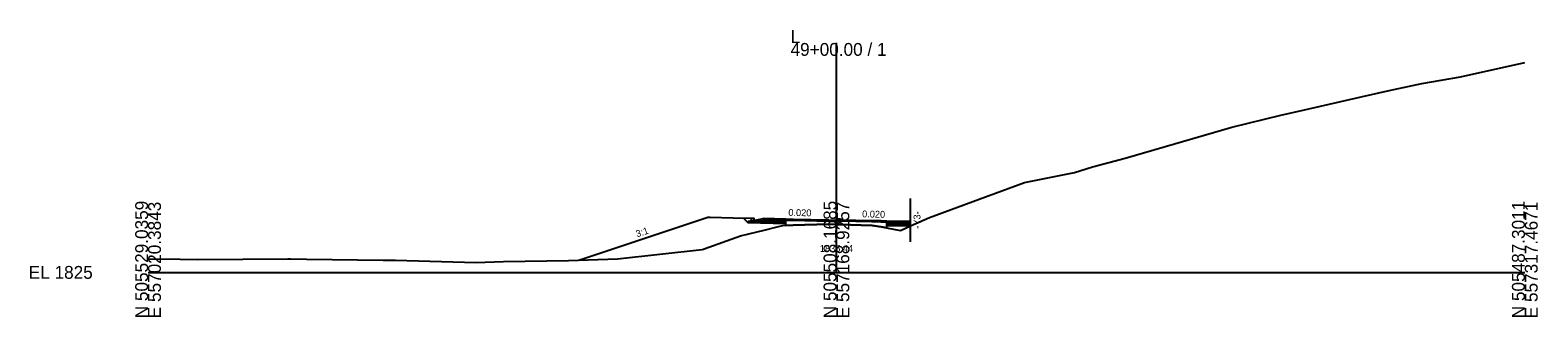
# Model space of a CAD drawing. Extents: x -26 to 4603, y -10 to 4703.
# Drawn here: x 1474.3 to 1802.8, y 4395.3 to 4457.8 of the extents above; entities that cross this region are included whole.
import ezdxf

# ---------------------------------------------------------------- set-up
doc = ezdxf.new("R2010")
doc.units = 0
for name, color, linetype in [('Default', 7, 'Continuous'), ('Exist Cross Section Cell', 7, 'Continuous'), ('Exist XS Ground Line', 7, 'Continuous'), ('Prop CMT Pvmt Course 1', 7, 'Continuous'), ('Prop CMT Pvmt Course 2', 7, 'Continuous'), ('Prop CMT Pvmt Course 3', 7, 'Continuous'), ('Prop CMT Pvmt Milling', 7, 'Continuous'), ('Prop CMT Shear Line', 7, 'Continuous'), ('Prop CMT Shld Paved Course 2', 7, 'Continuous'), ('Prop CMT Shld Paved Course 3', 7, 'Continuous'), ('Prop CMT Subgrade Earthwork', 7, 'Continuous'), ('Prop Conc Curb and Gutter', 7, 'Continuous'), ('Prop XS Finish Grade', 7, 'Continuous'), ('Prop XS Label Text', 7, 'Continuous'), ('Prop XS Shear Point Element', 7, 'Continuous'), ('Prop XS Shear Point Label', 7, 'Continuous'), ('Prop XS SS Elevation Text', 7, 'Continuous'), ('Scratch_Level_9', 7, 'Continuous')]:
    doc.layers.add(name, color=color, linetype=linetype)

msp = doc.modelspace()

# ---------------------------------------------------------------- linework, layer by layer
at = {"layer": 'Exist Cross Section Cell'}
for p, q in [((1650, 4405), (1650, 4455)), ((1500, 4405), (1650, 4405)), ((1650, 4405), (1800, 4405))]:
    msp.add_line(p, q, dxfattribs=at)
at = {"layer": 'Exist XS Ground Line'}
msp.add_lwpolyline([(1500, 4407.94), (1506.96, 4407.86), (1510.83, 4407.79), (1530.46, 4407.94), (1531.02, 4407.94), (1534.5, 4407.9), (1551.22, 4407.69), (1553.95, 4407.67), (1571.42, 4407.17), (1577.45, 4407.35), (1591.61, 4407.57), (1602.29, 4407.97), (1620.72, 4410.01), (1621, 4410.05), (1621.16, 4410.11), (1629.12, 4412.94), (1632.73, 4413.85), (1634.22, 4414.18), (1637.11, 4414.93), (1638.33, 4415.23), (1640.58, 4415.29), (1648.26, 4415.48), (1650.65, 4415.43), (1657.82, 4415.25), (1659.75, 4414.92), (1663.93, 4414.12), (1666.13, 4415.15), (1670.27, 4416.93), (1681.11, 4420.94), (1690.99, 4424.58), (1701.87, 4426.78), (1705.77, 4428.03), (1712.92, 4429.91), (1736.17, 4436.65), (1746.83, 4439.29), (1751.99, 4440.46), (1764.32, 4443.3), (1770.47, 4444.68), (1777.55, 4446.15), (1785.98, 4447.64), (1800, 4450.74)], dxfattribs=at)
at = {"layer": 'Prop CMT Pvmt Course 1'}
for points in [[(1639, 4416.63), (1634, 4416.73), (1634, 4416.48), (1634, 4416.48), (1639, 4416.38), (1639, 4416.38), (1639, 4416.38), (1639, 4416.63), (1639, 4416.63)], [(1650, 4416.41), (1650, 4416.41), (1650, 4415.44), (1650, 4415.44), (1650, 4415.44), (1648.26, 4415.48), (1648.26, 4415.48), (1640.58, 4415.29), (1640.58, 4415.29), (1639, 4415.25), (1639, 4415.25), (1639, 4416.63), (1640.58, 4416.6), (1640.58, 4416.6), (1648.26, 4416.45), (1648.26, 4416.45), (1650, 4416.41)], [(1659.75, 4416.22), (1657.82, 4416.26), (1657.82, 4416.26), (1650.65, 4416.4), (1650.65, 4416.4), (1650, 4416.41), (1650, 4415.44), (1650, 4415.44), (1650.65, 4415.43), (1650.65, 4415.43), (1657.82, 4415.25), (1657.82, 4415.25), (1659.75, 4414.92), (1659.75, 4414.92), (1661, 4414.68), (1661, 4414.68), (1661, 4416.19), (1659.75, 4416.22), (1659.75, 4416.22)], [(1661, 4416.19), (1661, 4416.19), (1661, 4415.94), (1661, 4415.94), (1661, 4415.94), (1666.14, 4415.84), (1666.14, 4415.84), (1666.14, 4416.09), (1661, 4416.19)]]:
    msp.add_lwpolyline(points, dxfattribs=at)
at = {"layer": 'Prop CMT Pvmt Course 2'}
for points in [[(1639, 4416.38), (1634, 4416.48), (1634, 4416.15), (1634, 4416.15), (1639, 4416.05), (1639, 4416.05), (1639, 4416.05), (1639, 4416.38), (1639, 4416.38)], [(1661, 4415.94), (1661, 4415.94), (1661, 4415.61), (1661, 4415.61), (1661, 4415.61), (1666.14, 4415.51), (1666.14, 4415.51), (1666.14, 4415.84), (1661, 4415.94)]]:
    msp.add_lwpolyline(points, dxfattribs=at)
at = {"layer": 'Prop CMT Pvmt Course 3'}
for points in [[(1639, 4416.05), (1634, 4416.15), (1634, 4415.78), (1634, 4415.78), (1639, 4415.68), (1639, 4415.68), (1639, 4415.68), (1639, 4416.05), (1639, 4416.05)], [(1661, 4415.61), (1661, 4415.61), (1661, 4415.24), (1661, 4415.24), (1661, 4415.24), (1666.14, 4415.13), (1666.14, 4415.13), (1666.14, 4415.51), (1661, 4415.61)]]:
    msp.add_lwpolyline(points, dxfattribs=at)
at = {"layer": 'Prop CMT Pvmt Milling'}
for points in [[(1639, 4415.25), (1640.58, 4415.29), (1640.58, 4415.29), (1648.26, 4415.48), (1648.26, 4415.48), (1650, 4415.44), (1650, 4415.44)], [(1661, 4414.68), (1659.75, 4414.92), (1659.75, 4414.92), (1657.82, 4415.25), (1657.82, 4415.25), (1650.65, 4415.43), (1650.65, 4415.43), (1650, 4415.44)]]:
    msp.add_lwpolyline(points, dxfattribs=at)
at = {"layer": 'Prop CMT Shld Paved Course 2'}
for points in [[(1650, 4416.16), (1650, 4416.16), (1650, 4415.44), (1650, 4415.44), (1650, 4415.44), (1648.26, 4415.48), (1648.26, 4415.48), (1640.58, 4415.29), (1640.58, 4415.29), (1639, 4415.25), (1639, 4415.25), (1639, 4416.38), (1640.58, 4416.35), (1640.58, 4416.35), (1648.26, 4416.2), (1648.26, 4416.2), (1650, 4416.16)], [(1659.75, 4415.97), (1657.82, 4416.01), (1657.82, 4416.01), (1650.65, 4416.15), (1650.65, 4416.15), (1650, 4416.16), (1650, 4415.44), (1650, 4415.44), (1650.65, 4415.43), (1650.65, 4415.43), (1657.82, 4415.25), (1657.82, 4415.25), (1659.75, 4414.92), (1659.75, 4414.92), (1661, 4414.68), (1661, 4414.68), (1661, 4415.94), (1659.75, 4415.97), (1659.75, 4415.97)]]:
    msp.add_lwpolyline(points, dxfattribs=at)
at = {"layer": 'Prop CMT Shld Paved Course 3'}
msp.add_lwpolyline([(1634, 4416.15), (1634, 4416.15), (1634, 4415.78), (1634, 4415.78), (1634, 4415.78), (1630.7, 4415.84), (1630.7, 4415.84), (1631, 4416.21), (1634, 4416.15)], dxfattribs=at)
at = {"layer": 'Prop CMT Subgrade Earthwork'}
for points in [[(1629.67, 4416.87), (1630.7, 4415.84), (1630.7, 4415.84)], [(1630.7, 4415.84), (1639, 4415.68), (1639, 4415.68)], [(1666.14, 4415.13), (1661, 4415.24)]]:
    msp.add_lwpolyline(points, dxfattribs=at)
at = {"layer": 'Prop Conc Curb and Gutter'}
msp.add_lwpolyline([(1632, 4416.33), (1634, 4416.73), (1634, 4416.15), (1634, 4416.15), (1634, 4416.15), (1631.5, 4416.2), (1631.5, 4416.2), (1631.5, 4416.83), (1632, 4416.83), (1632, 4416.83), (1632, 4416.33), (1632, 4416.33), (1632, 4416.33)], dxfattribs=at)
at = {"layer": 'Prop XS Finish Grade'}
msp.add_line((1622.5, 4417.01), (1627.5, 4416.91), dxfattribs=at)
for points in [[(1593.9, 4407.66), (1593.9, 4407.66), (1622, 4417.02)], [(1622, 4417.02), (1622.5, 4417.01), (1622.5, 4417.01)], [(1627.5, 4416.91), (1631.5, 4416.83), (1631.5, 4416.83)]]:
    msp.add_lwpolyline(points, dxfattribs=at)
at = {"layer": 'Prop XS Shear Point Element'}
msp.add_line((1666.14, 4411.64), (1666.14, 4421.13), dxfattribs=at)
at = {"layer": 'Scratch_Level_9'}
msp.add_lwpolyline([(1634, 4416.73), (1634, 4416.48)], dxfattribs=at)

# ---------------------------------------------------------------- texts
at = {"layer": 'Default'}
msp.add_text('-', height=0.0001, dxfattribs=at).set_placement((1500, 4405))
at = {"layer": 'Exist Cross Section Cell'}
for s, p in [('49+00.00 / 1', (1640, 4452.2)), ('L', (1640, 4455)), ('EL 1825', (1474, 4403.6))]:
    msp.add_text(s, height=2.8, dxfattribs=at).set_placement(p)
for s, p in [('N 505529.0359', (1500, 4395)), ('E 557020.3843', (1502.8, 4395)), ('N 505508.1685', (1650, 4395)), ('E 557168.9257', (1652.8, 4395)), ('N 505487.3011', (1800, 4395)), ('E 557317.4671', (1802.8, 4395))]:
    msp.add_text(s, height=2.8, rotation=90, dxfattribs=at).set_placement(p)
at = {"layer": 'Prop CMT Shear Line'}
for p in [(1622, 4417.02), (1622.5, 4417.01), (1627.5, 4416.91), (1632, 4416.33), (1634, 4416.73), (1634, 4416.73), (1650, 4416.41), (1666.14, 4416.09), (1593.9, 4407.66)]:
    msp.add_text('X', height=0.0025, dxfattribs=at).set_placement(p)
at = {"layer": 'Prop XS Label Text'}
for s, rotation, p in [('0.020', 358.8542, (1639.51, 4417.32)), ('0.020', 358.8542, (1655.58, 4417)), ('3:1', 18.4332, (1606.56, 4412.62))]:
    msp.add_text(s, height=1.5, rotation=rotation, dxfattribs=at).set_placement(p)
at = {"layer": 'Prop XS Shear Point Label'}
msp.add_text('-Y3-', height=1.5, rotation=90, dxfattribs=at).set_placement((1668.31, 4414.5))
at = {"layer": 'Prop XS SS Elevation Text'}
msp.add_text('1835.44', height=1.5, dxfattribs=at).set_placement((1646.38, 4409.47))

doc.saveas('drawing.dxf')
